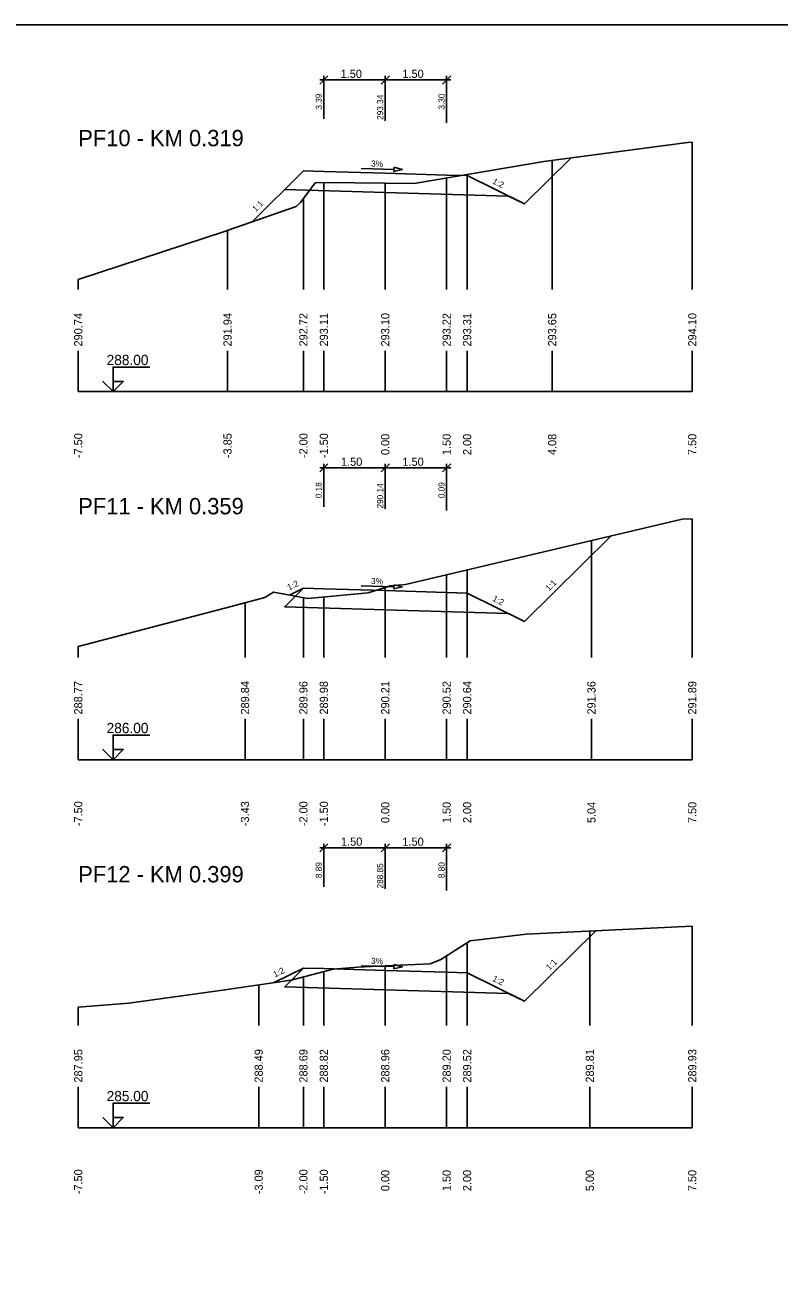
# Model space of a CAD drawing. Extents: x -5 to 1265, y -2 to 602.
# Drawn here: x 647 to 831.2, y 291.7 to 596.7 of the extents above; entities that cross this region are included whole.
import ezdxf

# ---------------------------------------------------------------- set-up
doc = ezdxf.new("R2010")
doc.units = 0
for name, color, linetype in [('KOTA', 7, 'Continuous'), ('KOTA_DELKY', 7, 'Continuous'), ('KOTA_DELKY_CONT', 7, 'Continuous'), ('NS_TELESO_VOZOVKY', 7, 'Continuous'), ('NS_V_PF', 7, 'Continuous'), ('REZY_PF_PUVODNI', 7, 'Continuous'), ('SESTAVY_REZU_PF', 7, 'Continuous'), ('SKLON', 7, 'Continuous'), ('SVK', 7, 'Continuous')]:
    doc.layers.add(name, color=color, linetype=linetype)

msp = doc.modelspace()

# ---------------------------------------------------------------- linework, layer by layer
msp.add_lwpolyline([(0, 596.67), (1260, 596.67), (1260, 2.67), (0, 2.67)], close=True)
at = {"layer": 'KOTA'}
for points in [[(668.51, 507), (666.01, 509.5), (668.51, 507), (668.51, 513), (677.51, 513)], [(668.51, 507), (671.01, 509.5), (668.51, 509.5), (668.51, 507)], [(668.51, 507), (671.01, 509.5), (668.51, 509.5)], [(668.51, 417), (666.01, 419.5), (668.51, 417), (668.51, 423), (677.51, 423)], [(668.51, 417), (671.01, 419.5), (668.51, 419.5), (668.51, 417)], [(668.51, 417), (671.01, 419.5), (668.51, 419.5)], [(668.51, 327), (666.01, 329.5), (668.51, 327), (668.51, 333), (677.51, 333)], [(668.51, 327), (671.01, 329.5), (668.51, 329.5), (668.51, 327)], [(668.51, 327), (671.01, 329.5), (668.51, 329.5)]]:
    msp.add_lwpolyline(points, dxfattribs=at)
at = {"layer": 'KOTA_DELKY'}
for points in [[(719, 582.22), (721, 584.22)], [(719, 583.22), (736, 583.22)], [(720, 573.67), (720, 584.22)], [(734, 582.22), (736, 584.22)], [(734, 582.22), (736, 584.22)], [(734, 583.22), (751, 583.22)], [(735, 573.22), (735, 584.22)], [(735, 573.22), (735, 584.22)], [(749, 582.22), (751, 584.22)], [(750, 572.77), (750, 584.22)], [(719, 487.36), (721, 489.36)], [(719, 488.36), (736, 488.36)], [(720, 478.81), (720, 489.36)], [(734, 487.36), (736, 489.36)], [(734, 487.36), (736, 489.36)], [(734, 488.36), (751, 488.36)], [(735, 478.36), (735, 489.36)], [(735, 478.36), (735, 489.36)], [(749, 487.36), (751, 489.36)], [(750, 477.91), (750, 489.36)], [(719, 394.46), (721, 396.46)], [(720, 385.91), (720, 396.46)], [(734, 394.46), (736, 396.46)], [(734, 394.46), (736, 396.46)], [(735, 385.46), (735, 396.46)], [(735, 385.46), (735, 396.46)], [(749, 394.46), (751, 396.46)], [(750, 385.01), (750, 396.46)], [(719, 395.46), (736, 395.46)], [(734, 395.46), (751, 395.46)]]:
    msp.add_lwpolyline(points, dxfattribs=at)
at = {"layer": 'NS_TELESO_VOZOVKY'}
for points in [[(735, 560.42), (750, 559.97), (755, 559.82), (769.01, 552.89), (765.11, 554.82), (735, 555.72), (710.44, 556.46), (715, 561.02), (720, 560.87), (735, 560.42)], [(735, 458.36), (750, 457.91), (755, 457.76), (769.01, 450.83), (765.11, 452.75), (735, 453.66), (710.44, 454.39), (715, 458.96), (720, 458.81), (735, 458.36)], [(735, 365.46), (750, 365.01), (755, 364.86), (769.01, 357.92), (765.11, 359.85), (735, 360.76), (710.44, 361.49), (715, 366.06), (720, 365.91), (735, 365.46)]]:
    msp.add_lwpolyline(points, dxfattribs=at)
at = {"layer": 'NS_V_PF'}
for points in [[(702.5, 548.53), (715, 561.02), (720, 560.87), (735, 560.42), (750, 559.97), (755, 559.82), (769.01, 552.89), (780.35, 564.11)], [(711.6, 457.26), (715, 458.96), (720, 458.81), (735, 458.36), (750, 457.91), (755, 457.76), (769.01, 450.83), (790.07, 471.68)], [(707.85, 362.48), (715, 366.06), (720, 365.91), (735, 365.46), (750, 365.01), (755, 364.86), (769.01, 357.92), (786.41, 375.15)]]:
    msp.add_lwpolyline(points, dxfattribs=at)
at = {"layer": 'REZY_PF_PUVODNI'}
for points in [[(660, 534.41), (695.94, 546.22), (696.61, 546.46), (713.21, 552.28), (714.28, 553.24), (717.84, 558.04), (720.19, 558.14), (735, 557.97), (742.05, 557.88), (773.75, 563.24), (808.8, 567.91), (810, 568)], [(660, 444.68), (697.37, 454.48), (705.58, 456.64), (707.74, 457.98), (716.1, 456.41), (730.84, 457.8), (735, 459.11), (736.18, 459.48), (739.91, 459.8), (807.5, 475.8), (807.55, 475.82), (810, 475.93)], [(660, 356.5), (672.37, 357.43), (694.07, 360.52), (712.04, 363.08), (722.25, 365.81), (728.29, 366.23), (735, 366.56), (745.96, 367.11), (748.61, 368.15), (755.76, 372.74), (769.41, 374.32), (784.52, 375.06), (810, 376.3)]]:
    msp.add_lwpolyline(points, dxfattribs=at)
at = {"layer": 'SESTAVY_REZU_PF'}
for points in [[(660, 507), (810, 507)], [(660, 417), (810, 417)], [(660, 327), (810, 327)]]:
    msp.add_lwpolyline(points, dxfattribs=at)
at = {"layer": 'SKLON'}
for points in [[(729.15, 561.6), (737.14, 561.36)], [(737.16, 561.86), (739.14, 561.3), (737.13, 560.86), (737.16, 561.86)], [(729.15, 459.53), (737.14, 459.29)], [(737.16, 459.79), (739.14, 459.23), (737.13, 458.79), (737.16, 459.79)], [(729.15, 366.63), (737.14, 366.39)], [(737.16, 366.89), (739.14, 366.33), (737.13, 365.89), (737.16, 366.89)]]:
    msp.add_lwpolyline(points, dxfattribs=at)
for points in [[(737.16, 561.86), (739.14, 561.3), (737.13, 560.86)], [(737.16, 459.79), (739.14, 459.23), (737.13, 458.79)], [(737.16, 366.89), (739.14, 366.33), (737.13, 365.89)]]:
    msp.add_lwpolyline(points, close=True, dxfattribs=at)
at = {"layer": 'SVK'}
for points in [[(810, 532), (810, 568)], [(775.78, 532), (775.78, 563.51)], [(720, 532), (720, 558.13)], [(750, 532), (750, 559.22)], [(755, 532), (755, 560.07)], [(735, 532), (735, 557.97)], [(715, 532), (715, 554.21)], [(696.47, 532), (696.47, 546.41)], [(660, 532), (660, 534.41)], [(660, 507), (660, 517)], [(696.47, 507), (696.47, 517)], [(715, 507), (715, 517)], [(720, 507), (720, 517)], [(735, 507), (735, 517)], [(750, 507), (750, 517)], [(755, 507), (755, 517)], [(775.78, 507), (775.78, 517)], [(810, 507), (810, 517)], [(810, 442), (810, 475.93)], [(785.37, 442), (785.37, 470.57)], [(750, 442), (750, 462.19)], [(755, 442), (755, 463.38)], [(735, 442), (735, 459.11)], [(700.74, 442), (700.74, 455.37)], [(715, 442), (715, 456.62)], [(720, 442), (720, 456.78)], [(660, 442), (660, 444.68)], [(660, 417), (660, 427)], [(700.74, 417), (700.74, 427)], [(715, 417), (715, 427)], [(720, 417), (720, 427)], [(735, 417), (735, 427)], [(750, 417), (750, 427)], [(755, 417), (755, 427)], [(785.37, 417), (785.37, 427)], [(810, 417), (810, 427)], [(810, 352), (810, 376.3)], [(755, 352), (755, 372.25)], [(784.98, 352), (784.98, 375.08)], [(750, 352), (750, 369.04)], [(735, 352), (735, 366.56)], [(715, 352), (715, 363.87)], [(720, 352), (720, 365.21)], [(704.08, 352), (704.08, 361.94)], [(660, 352), (660, 356.5)], [(660, 327), (660, 337)], [(704.08, 327), (704.08, 337)], [(715, 327), (715, 337)], [(720, 327), (720, 337)], [(735, 327), (735, 337)], [(750, 327), (750, 337)], [(755, 327), (755, 337)], [(784.98, 327), (784.98, 337)], [(810, 327), (810, 337)]]:
    msp.add_lwpolyline(points, dxfattribs=at)

# ---------------------------------------------------------------- texts
at = {"layer": 'KOTA'}
for s, p in [('288.00', (666.93, 513.5)), ('286.00', (666.93, 423.5)), ('285.00', (666.93, 333.5))]:
    msp.add_text(s, height=2.5, dxfattribs=at).set_placement(p)
at = {"layer": 'KOTA_DELKY'}
for p in [(724.1, 583.72), (739.19, 583.72), (724.19, 488.86), (739.19, 488.86), (724.19, 395.96), (739.19, 395.96)]:
    msp.add_text('1.50', height=2, dxfattribs=at).set_placement(p)
at = {"layer": 'KOTA_DELKY_CONT'}
for s, p in [('3.39', (719.5, 575.97)), ('293.34', (734.5, 573.46)), ('3.30', (749.5, 575.97)), ('0.18', (719.5, 480.95)), ('290.14', (734.5, 478.43)), ('0.09', (749.5, 480.95)), ('8.89', (719.5, 388.05)), ('288.85', (734.5, 385.53)), ('8.80', (749.5, 388.05))]:
    msp.add_text(s, height=1.5, rotation=90, dxfattribs=at).set_placement(p)
at = {"layer": 'SESTAVY_REZU_PF'}
for s, p in [('PF10 - KM 0.319', (660, 567)), ('PF11 - KM 0.359', (660, 477)), ('PF12 - KM 0.399', (660, 387))]:
    msp.add_text(s, height=4, dxfattribs=at).set_placement(p)
at = {"layer": 'SKLON'}
for s, rotation, p in [('3%', 358.2816, (731.52, 562.03)), ('1:2', 333.679, (761.04, 557.95)), ('1:1', 45, (703.42, 550.85)), ('1:2', 26.5651, (711.52, 458.34)), ('3%', 358.2816, (731.52, 459.96)), ('1:1', 44.7149, (774.98, 458.14)), ('1:2', 333.679, (761.04, 455.89)), ('1:2', 26.5651, (708.07, 363.71)), ('3%', 358.2816, (731.52, 367.06)), ('1:1', 44.7149, (775.13, 365.39)), ('1:2', 333.679, (761.04, 362.99))]:
    msp.add_text(s, height=1.5, rotation=rotation, dxfattribs=at).set_placement(p)
at = {"layer": 'SVK'}
for s, p in [(' 290.74', (661, 517.3)), (' 291.94', (697.47, 517.3)), (' 292.72', (716, 517.3)), (' 293.11', (721, 517.3)), (' 293.10', (736, 517.3)), (' 293.22', (751, 517.3)), (' 293.31', (756, 517.3)), (' 293.65', (776.78, 517.3)), (' 294.10', (811, 517.3)), (' -7.50', (661, 490)), (' -3.85', (697.47, 490)), (' -2.00', (716, 490)), (' -1.50', (721, 490)), ('  0.00', (736, 490)), ('  1.50', (751, 490)), ('  2.00', (756, 490)), ('  4.08', (776.78, 490)), ('  7.50', (811, 490)), (' 288.77', (661, 427.3)), (' 289.84', (701.74, 427.3)), (' 289.96', (716, 427.3)), (' 289.98', (721, 427.3)), (' 290.21', (736, 427.3)), (' 290.52', (751, 427.3)), (' 290.64', (756, 427.3)), (' 291.36', (786.37, 427.3)), (' 291.89', (811, 427.3)), (' -7.50', (661, 400)), (' -3.43', (701.74, 400)), (' -2.00', (716, 400)), (' -1.50', (721, 400)), ('  0.00', (736, 400)), ('  1.50', (751, 400)), ('  2.00', (756, 400)), ('  5.04', (786.37, 400)), ('  7.50', (811, 400)), (' 287.95', (661, 337.3)), (' 288.49', (705.08, 337.3)), (' 288.69', (716, 337.3)), (' 288.82', (721, 337.3)), (' 288.96', (736, 337.3)), (' 289.20', (751, 337.3)), (' 289.52', (756, 337.3)), (' 289.81', (785.98, 337.3)), (' 289.93', (811, 337.3)), (' -7.50', (661, 310)), (' -3.09', (705.08, 310)), (' -2.00', (716, 310)), (' -1.50', (721, 310)), ('  0.00', (736, 310)), ('  1.50', (751, 310)), ('  2.00', (756, 310)), ('  5.00', (785.98, 310)), ('  7.50', (811, 310))]:
    msp.add_text(s, height=2, rotation=90, dxfattribs=at).set_placement(p)

doc.saveas('drawing.dxf')
